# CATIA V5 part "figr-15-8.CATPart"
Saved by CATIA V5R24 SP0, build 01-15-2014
Part number: Part1
Bounding box of the stored display mesh (mm): x -50 to 50, y -32.5 to 33.5, z -52 to 1
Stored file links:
  D:\KAVITA\CATIA V5-6R2014 Project_ Kavita\CATIA V5-6R2014_partfiles\Partfiles\c15_catia_v5-6r2014_prt\figr-15-8.CATPart
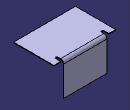
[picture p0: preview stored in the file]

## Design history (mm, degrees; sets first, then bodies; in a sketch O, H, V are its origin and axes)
SheetMetalParameters1: Thickness 1, BendRadius 4, KFactor 0.475772 {= log(min(100,max(20*SheetMetalParameters1.BendRadius,SheetMetalParameters1.Thickness)/SheetMetalParameters1.Thickness))/log(100)/2}, ReliefRadialLength 4, ReliefAxialLength 4, MinimumBendRadius 0
Body1 (main body)
  Sketch1 on xy-plane, origin (0, 0, 0), H (1, 0, 0), V (0, 1, 0)
    line L1 (-50, 32.5) -> (50, 32.5)
    line L2 (50, 32.5) -> (50, -32.5)
    line L3 (50, -32.5) -> (-50, -32.5)
    line L4 (-50, -32.5) -> (-50, 32.5)
    length L1 = 100
    length L2 = 65
    horizontal: L1 H, L3 H
    vertical: L2 V, L4 V
    symmetry: L4 L2 V, L1 L3 H
  Wall1: Thickness 1, Profile Sketch1
  d_NewWallOnEdge1: NewWallOnEdge_Edge edge [face of Wall1 | face of Wall1], NewWallOnEdge_Length 53, NewWallOnEdge_HeightLimitOffset 0, NewWallOnEdge_WidthOffset1 -15, NewWallOnEdge_WidthOffset2 -15, NewWallOnEdge_Angle 90, NewWallOnEdge_BendRadiusValue 4 {= SheetMetalParameters1.BendRadius}, NewWallOnEdge_BendTable SheetMetalParameters1, KFacteur 0.475772 {= log(min(100,max(20*d_NewWallOnEdge1.Radius,SheetMetalParameters1.Thickness)/SheetMetalParameters1.Thickness))/log(100)/2}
